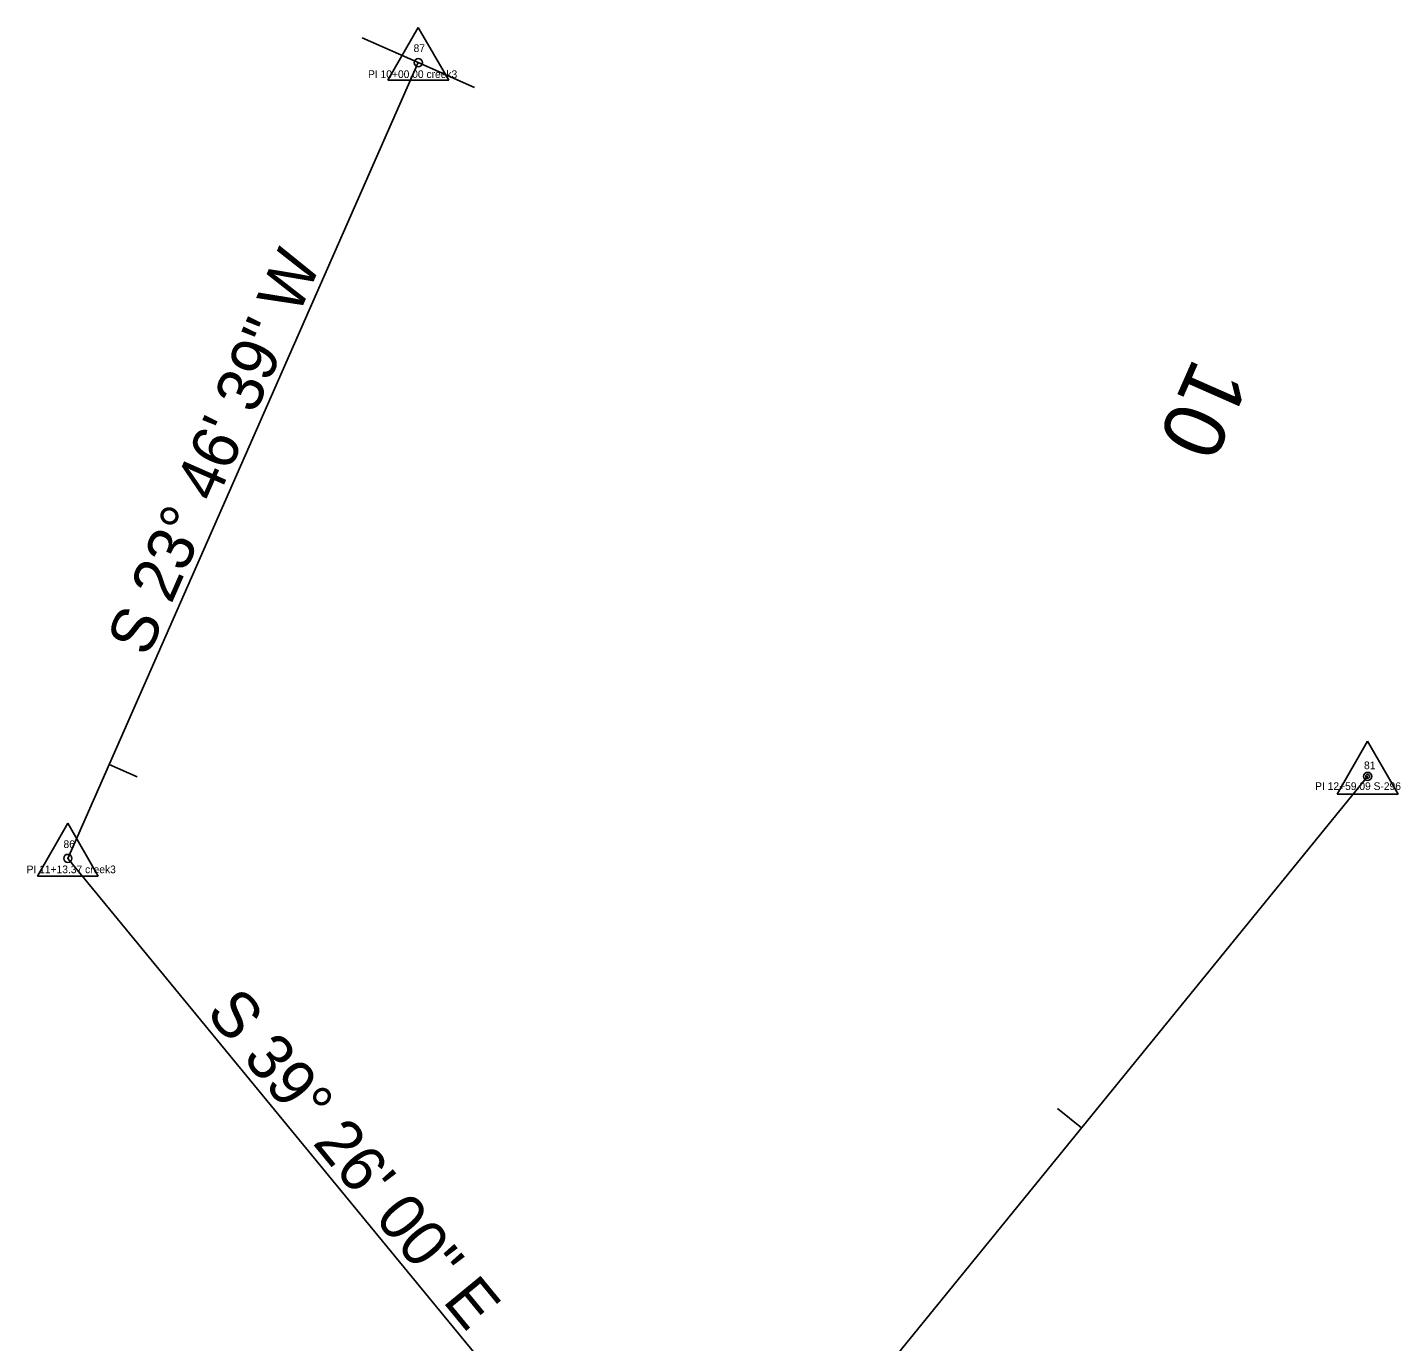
# Model space of a CAD drawing. Extents: x 1815672 to 1818258, y 1179223 to 1179901.
# Drawn here: x 1818065.5 to 1818244.5, y 1179729.6 to 1179900.9 of the extents above; entities that cross this region are included whole.
import ezdxf

# ---------------------------------------------------------------- set-up
doc = ezdxf.new("R2010")
doc.units = 0
for name, color, linetype in [('RD_EX_Misc', 7, 'Continuous'), ('RD_EX_Misc_txCode', 7, 'Continuous'), ('RD_HC_CL', 7, 'Continuous'), ('RD_HC_Data_Tic', 7, 'Continuous'), ('RD_HC_TX_Sta50', 7, 'Continuous'), ('RD_SMD_Locator', 7, 'Continuous')]:
    doc.layers.add(name, color=color, linetype=linetype)

msp = doc.modelspace()

# ---------------------------------------------------------------- linework, layer by layer
at = {"layer": 'RD_EX_Misc'}
for p, q in [((1818112.47, 1179894.02), (1818116.44, 1179900.9)), ((1818116.44, 1179900.9), (1818120.41, 1179894.02)), ((1818112.47, 1179894.02), (1818120.41, 1179894.02)), ((1818236.26, 1179800.96), (1818240.23, 1179807.84)), ((1818240.23, 1179807.84), (1818244.2, 1179800.96)), ((1818236.26, 1179800.96), (1818244.2, 1179800.96)), ((1818066.76, 1179790.27), (1818070.74, 1179797.15)), ((1818070.74, 1179797.15), (1818074.7, 1179790.27)), ((1818066.76, 1179790.27), (1818074.7, 1179790.27))]:
    msp.add_line(p, q, dxfattribs=at)
for centre in [(1818116.44, 1179896.31), (1818240.23, 1179803.26), (1818070.73, 1179792.57)]:
    msp.add_circle(centre, 0.529, dxfattribs=at)
at = {"layer": 'RD_HC_CL'}
for p, q in [((1818116.44, 1179896.31), (1818070.73, 1179792.57)), ((1818076.61, 1179602.37), (1818240.23, 1179803.26)), ((1818070.73, 1179792.57), (1818139.56, 1179708.88))]:
    msp.add_line(p, q, dxfattribs=at)
at = {"layer": 'RD_HC_Data_Tic'}
for p, q in [((1818116.44, 1179896.31), (1818109.12, 1179899.54)), ((1818116.44, 1179896.31), (1818123.76, 1179893.09)), ((1818076.12, 1179804.8), (1818079.78, 1179803.19)), ((1818202.91, 1179757.44), (1818199.81, 1179759.97))]:
    msp.add_line(p, q, dxfattribs=at)
at = {"layer": 'RD_SMD_Locator'}
for centre, radius in [((1818116.44, 1179896.31), 0.001), ((1818240.23, 1179803.26), 0.25), ((1818240.23, 1179803.26), 0.001), ((1818070.73, 1179792.57), 0.001)]:
    msp.add_circle(centre, radius, dxfattribs=at)

# ---------------------------------------------------------------- texts
at = {"layer": 'RD_EX_Misc'}
for s, rotation, p in [('S 23%%d 46\' 39" W', 66.2226, (1818081.15, 1179818.68)), ('S 39%%d 26\' 00" E', 309.4333, (1818088.61, 1179772.4))]:
    msp.add_text(s, height=6, rotation=rotation, dxfattribs=at).set_placement(p)
at = {"layer": 'RD_EX_Misc_txCode'}
for s, p in [('87', (1818115.82, 1179897.7)), ('PI 10+00.00 creek3', (1818109.88, 1179894.31)), ('81', (1818239.76, 1179804.2)), ('PI 12+59.09 S-296', (1818233.39, 1179801.49)), ('86', (1818070.17, 1179793.93)), ('PI 11+13.37 creek3', (1818065.36, 1179790.64))]:
    msp.add_text(s, height=1, dxfattribs=at).set_placement(p)
at = {"layer": 'RD_HC_TX_Sta50'}
msp.add_text('10', height=8, rotation=246.2226, dxfattribs=at).set_placement((1818217.61, 1179858.07))

doc.saveas('drawing.dxf')
